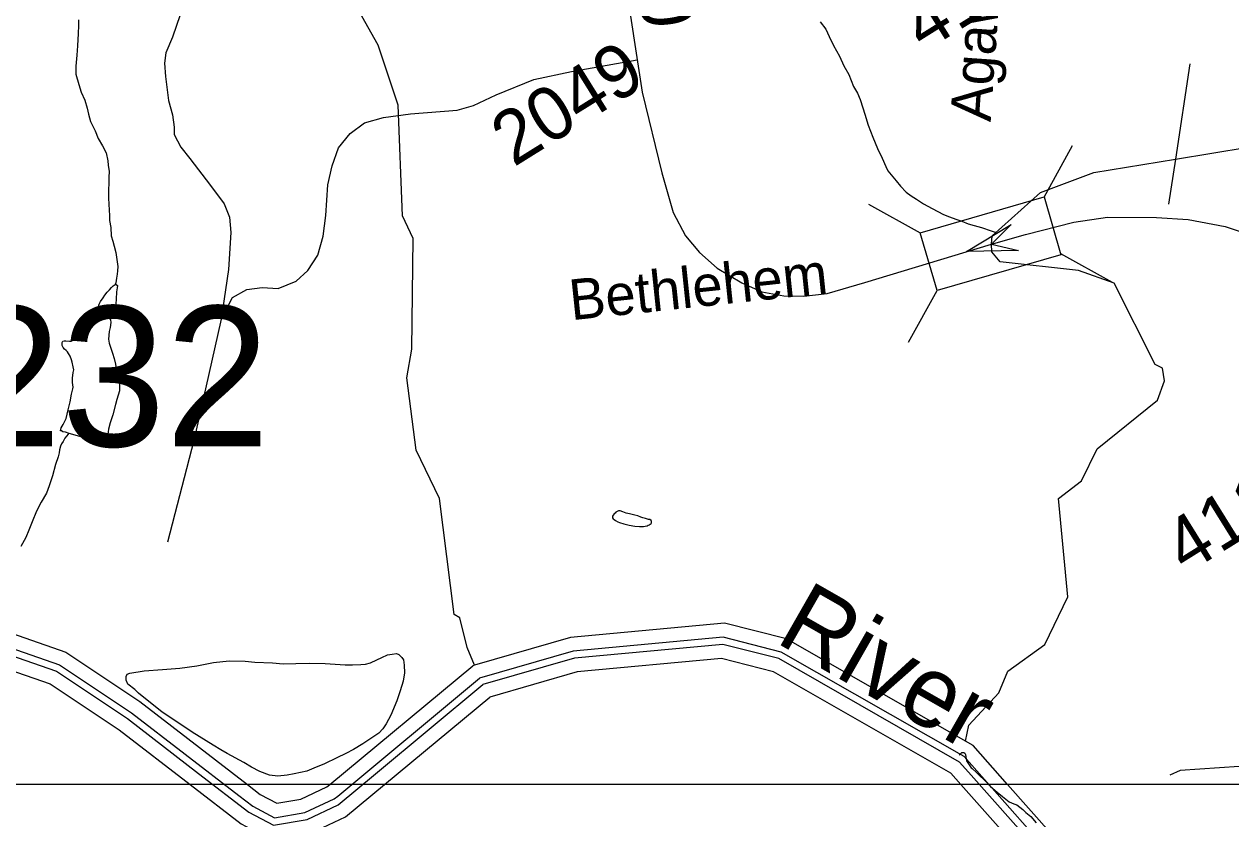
# Model space of a CAD drawing. Extents: x 2001466 to 31450019, y -30647475 to 847247.
# Drawn here: x 2150565 to 2156218, y 718722 to 722442 of the extents above; entities that cross this region are included whole.
import ezdxf

# ---------------------------------------------------------------- set-up
doc = ezdxf.new("R2010")
doc.units = 0
for name, color, linetype in [('Exist Hydrographic Buffer Line', 7, 'Continuous'), ('Exist Hydrographic Creek Single Shore', 7, 'Continuous'), ('Exist Hydrographic Misc Water Feature', 7, 'Continuous'), ('Exist Hydrographic River Shore', 7, 'Continuous'), ('Exist Hydrographic River Shore Label', 7, 'Continuous'), ('Exist Road Non-System Type 51', 7, 'Continuous'), ('Exist Road Secondary Mileage Hundredths English Label', 7, 'Continuous'), ('Exist Road Secondary Structure Standard Bridge Attributed CELL', 7, 'Continuous'), ('Exist Road Secondary Structure Standard Bridge CELL', 7, 'Continuous'), ('Exist Road Secondary Structure Standard Bridge Number Label', 7, 'Continuous'), ('Exist Road Secondary Type 51 Attributed', 7, 'Continuous'), ('Exist Road Secondary Type 51 Label', 7, 'Continuous'), ('Exist Road Secondary Type 51 Number Label', 7, 'Continuous'), ('Map Preparation Inset Cut Line', 7, 'Continuous')]:
    doc.layers.add(name, color=color, linetype=linetype)

msp = doc.modelspace()

# ---------------------------------------------------------------- linework, layer by layer
at = {"layer": 'Exist Hydrographic Buffer Line'}
for p, q in [((2152034.3, 718828.8), (2152699.3, 719379.8)), ((2152212.1, 718933.4), (2152714.9, 719350.2)), ((2155123.4, 718839.4), (2154968.6, 719013.7)), ((2155002.2, 718926.5), (2154947.7, 718987.9))]:
    msp.add_line(p, q, dxfattribs=at)
for points in [[(2148481.3, 719308.3), (2149005.6, 719433.8), (2149630.9, 719486.7), (2150073, 719573), (2150393.3, 719559.8), (2150731.4, 719443.3), (2151068.7, 719218.4), (2151571.1, 718831)], [(2154968.6, 719013.7), (2154112.4, 719502.7), (2153840.5, 719571.7), (2153137.1, 719506.8), (2152699.3, 719379.8)], [(2148486, 719275.6), (2149010.8, 719401.4), (2149635.4, 719454.2), (2150075.5, 719540.1), (2150387.1, 719527.2), (2150716.7, 719413.6), (2151049.5, 719191.8), (2151382.6, 718934.9)], [(2154947.7, 718987.9), (2154100, 719472), (2153837.9, 719538.5), (2153143.2, 719474.5), (2152714.9, 719350.2)], [(2151382.6, 718934.9), (2151618.2, 718753.2), (2151733.5, 718691.9), (2151891.1, 718719.7), (2152036, 718787.5), (2152212.1, 718933.4)], [(2155296.9, 718594.5), (2155002.2, 718926.5)], [(2151571.1, 718831), (2151636, 718780.9), (2151738.9, 718726.2), (2151881.1, 718751.3), (2152018.3, 718815.5), (2152034.3, 718828.8)], [(2155325.2, 718612), (2155123.4, 718839.4)]]:
    msp.add_lwpolyline(points, dxfattribs=at)
at = {"layer": 'Exist Hydrographic Creek Single Shore'}
for points in [[(2155958.2, 721810.2), (2156300, 721866.7), (2156766.1, 722011.4), (2156882.2, 722087.7), (2156907.2, 722169.2), (2156940.2, 722188.2)], [(2154975.6, 719085.3), (2154991.2, 719160.9), (2155132, 719312.2), (2155173.1, 719413), (2155347.1, 719537.4), (2155454.2, 719761.6), (2155410.1, 720221.7), (2155518.2, 720304.8), (2155592.2, 720454.2), (2155874.1, 720681.3), (2155907.1, 720772.5), (2155898.1, 720831.7), (2155864.1, 720848.8), (2155671.1, 721230), (2155504, 721289.2), (2155137.8, 721330.1), (2155098.3, 721375.6), (2155096.8, 721412.2), (2155100.5, 721451.8), (2155327.1, 721653.7), (2155576.2, 721747), (2155958.2, 721810.2)]]:
    msp.add_lwpolyline(points, dxfattribs=at)
at = {"layer": 'Exist Hydrographic Misc Water Feature'}
msp.add_line((2150947.3, 721103.3), (2150942.2, 721079.3), dxfattribs=at)
for points in [[(2152675, 719441.1), (2152640.1, 719523.8), (2152606.2, 719662.3), (2152580.2, 719679.2), (2152511.1, 720221.9), (2152401.2, 720447.2), (2152358.1, 720786), (2152382.1, 720920), (2152387.2, 721438.2), (2152337.2, 721544.2), (2152317.1, 722062.9), (2152224.2, 722343.6), (2152056.3, 722642.3), (2151988.2, 722843.8), (2151986.1, 723132.5), (2152027.1, 723374.4), (2152027.4, 723375.1)], [(2150820, 722461.9), (2150820, 722436), (2150818, 722398.1), (2150814.7, 722340.2), (2150812.8, 722296.3), (2150807.1, 722246), (2150807.7, 722208.3), (2150821.6, 722160.3), (2150831.9, 722124.3), (2150849.7, 722086.7), (2150860, 722048.6), (2150866.4, 722020.5), (2150876.4, 721986.5), (2150898.5, 721942.6), (2150912.9, 721906.8), (2150933.2, 721872.8), (2150949.2, 721839.2), (2150957.8, 721803), (2150959.6, 721781.2), (2150963.8, 721753), (2150961.7, 721725.4), (2150962.3, 721695.3), (2150960.5, 721669.2), (2150960.5, 721631), (2150962.5, 721597), (2150963.1, 721575.1), (2150965, 721543.1), (2150965.2, 721523.3), (2150971.3, 721489.4), (2150973.6, 721451.4), (2150981.6, 721425.5), (2150987.5, 721403.4), (2150995.7, 721373.4), (2150998.2, 721351.5), (2151004.4, 721307.6), (2151002.3, 721287.6), (2151000.5, 721271.7), (2150998.8, 721253.7), (2150994.7, 721231.6), (2150992.5, 721223.4)], [(2154294.8, 722453.5), (2154321.1, 722417.9), (2154337.1, 722383.9), (2154357.4, 722342.3), (2154385.7, 722292.2), (2154406, 722246.5), (2154428.3, 722206.6), (2154450.5, 722150.5), (2154468.5, 722119), (2154481, 722088.7), (2154495, 722050.9), (2154503.2, 722020.9), (2154519.1, 721969), (2154541.7, 721913.2), (2154562.2, 721859.4), (2154584.2, 721815.5), (2154602.6, 721775.8), (2154610.8, 721755.5), (2154634.6, 721728), (2154650.8, 721708.1), (2154671.1, 721683.9), (2154696.9, 721656.1), (2154721.3, 721638.3), (2154745.3, 721622.4), (2154779.2, 721600.7), (2154819.8, 721578.7), (2154845.4, 721565.1), (2154871.6, 721551.4), (2154899.9, 721539.4), (2154929.7, 721529.6), (2154957.8, 721519.7), (2154987.7, 721507.9), (2155015.8, 721500), (2155049.8, 721490.4), (2155096, 721474.5), (2155118.1, 721466.7)], [(2150947.3, 721103.3), (2150943.5, 721107.1), (2150925.4, 721111.1), (2150911.7, 721115.2), (2150917.2, 721131), (2150922.9, 721143.1), (2150935.5, 721161.1), (2150943.2, 721173.3), (2150955.1, 721187.3), (2150965.2, 721199.1), (2150974.8, 721209.4), (2150983, 721217.5), (2150992.5, 721223.4)], [(2150992.5, 721223.4), (2150996.8, 721223.6), (2151002.9, 721219.4), (2151000.9, 721207.5), (2150998.8, 721189.6), (2150998.8, 721179.5), (2150997, 721163.5), (2150997.2, 721151.7), (2150995.3, 721135.4), (2150993.5, 721119.4), (2150995.3, 721107.8), (2150995.5, 721093.5), (2150995.3, 721089.5), (2150989.2, 721091.6), (2150973.4, 721095.3), (2150957.4, 721101.4), (2150947.3, 721103.3)], [(2150776.5, 720526.4), (2150758.9, 720532.3), (2150746.4, 720534.2), (2150740.7, 720538.3), (2150736.3, 720538.1), (2150738.8, 720552.4), (2150748.7, 720568.3), (2150762.2, 720596.2), (2150772.4, 720636.5), (2150781.7, 720674.5), (2150787.6, 720710.4), (2150793.4, 720734.3), (2150795.6, 720742.5), (2150791.5, 720764.6), (2150791.5, 720784.5), (2150795.4, 720810.7), (2150798.9, 720824.4), (2150795, 720838.4), (2150790.9, 720860.4), (2150787, 720870.3), (2150780.6, 720888.3), (2150772.6, 720900.5), (2150768.7, 720908.4), (2150762.6, 720914.2), (2150754.6, 720920.3), (2150748.2, 720928.2), (2150744.3, 720938.1), (2150744.1, 720952.3), (2150746.4, 720958.1), (2150752.3, 720960.4), (2150760.3, 720960.4), (2150778.4, 720958.5), (2150786.4, 720958.5), (2150800.1, 720964.5), (2150807.9, 720972.7), (2150815.9, 720982.4), (2150830.3, 721002.5), (2150832.3, 721008.7), (2150837.8, 721024.5), (2150851.8, 721054.8), (2150861.8, 721068.8), (2150879.5, 721081.1), (2150897.7, 721083.2), (2150915.6, 721082.9), (2150923.8, 721081.3), (2150942.2, 721079.3)], [(2150942.2, 721079.3), (2150957.4, 721071.3), (2150963.5, 721067.5), (2150969.5, 721057.3), (2150971.7, 721045.6), (2150967.9, 721021.5), (2150964, 721003.4), (2150960.1, 720967.5), (2150964.4, 720949.4), (2150978.7, 720901.4), (2150986.7, 720877.5), (2150992.7, 720849.8), (2150997, 720829.7), (2151005, 720803.7), (2151007.6, 720775.8), (2151011.5, 720755.7), (2151011.5, 720725.7), (2150999.8, 720685.6), (2150993.7, 720661.9), (2150980.2, 720613.6), (2150968.3, 720575.6), (2150960.7, 720545.5), (2150956.8, 720521.4), (2150952.9, 720505.3), (2150952.7, 720499.7), (2150952.7, 720479.4), (2150923.2, 720485.5), (2150889.1, 720495.1), (2150860.8, 720501), (2150830.9, 720510.8), (2150805, 720518.8), (2150776.5, 720526.4)], [(2150776.5, 720526.4), (2150771.2, 720522.3), (2150756.6, 720504.2), (2150748.9, 720488.3), (2150740.9, 720478.2), (2150735.1, 720466.1), (2150731, 720450.1), (2150729.2, 720436.1), (2150725.5, 720416.5), (2150711.7, 720380.4), (2150698, 720328.1), (2150682.4, 720280.2), (2150670.3, 720245.9), (2150644.7, 720204), (2150623.2, 720161.8), (2150602.9, 720111.7), (2150587.7, 720073.5), (2150573.9, 720039.4), (2150549.8, 719997.2)], [(2153426.4, 720143.4), (2153401.8, 720149.6), (2153385.8, 720153.2), (2153369.8, 720159.3), (2153357.7, 720163.1), (2153354, 720163.3), (2153349.7, 720163.1), (2153344, 720161.2), (2153337.6, 720157.2), (2153333.9, 720152.9), (2153330.1, 720149.1), (2153324.3, 720143), (2153321.8, 720138.9), (2153322.1, 720134.9), (2153321.8, 720130.8), (2153324.1, 720126.8), (2153329.8, 720123.1), (2153336, 720119), (2153346, 720113), (2153354.5, 720109.3), (2153374.1, 720103.4), (2153400.4, 720097.4), (2153426.2, 720091.5), (2153448.4, 720089.8), (2153456.6, 720089.8), (2153466.4, 720089.9), (2153474.4, 720092), (2153484.5, 720094.1), (2153488.1, 720096), (2153494.5, 720097.9), (2153498.6, 720102.1), (2153502.3, 720104), (2153504.1, 720108.1), (2153504.3, 720113.8), (2153502.1, 720118.2), (2153496.1, 720123.9), (2153490.2, 720124), (2153476, 720127.8), (2153464, 720131.6), (2153454.1, 720133.5), (2153440.2, 720139.7), (2153426.4, 720143.4)], [(2152341.9, 719465.8), (2152346.4, 719441.5), (2152346.8, 719405.8), (2152340.7, 719365.8), (2152327.3, 719321.5), (2152311.1, 719273.7), (2152283.7, 719207.3), (2152261.9, 719167.1), (2152246.1, 719143.2), (2152226.3, 719123.1), (2152194.1, 719101.1), (2152152.4, 719072.6), (2152108.6, 719046.3), (2152072.7, 719028.3), (2152030.6, 719008.2), (2151973.2, 718979.6), (2151923.2, 718959.6), (2151889.4, 718945.3), (2151831.1, 718933), (2151797.5, 718926.7), (2151753.4, 718922.4), (2151715.3, 718926.1), (2151669.3, 718944), (2151631, 718964), (2151595.1, 718985.7), (2151516.6, 719027.2), (2151486.8, 719045.1), (2151450.5, 719066.8), (2151352.5, 719128.3), (2151209.8, 719223.3), (2151141.3, 719277), (2151101.5, 719310.6), (2151083.3, 719326.8), (2151051.1, 719352.3), (2151043.1, 719370.6), (2151042.9, 719380.3), (2151043.1, 719388.4), (2151048.8, 719398.5), (2151060.9, 719404.4), (2151127, 719414.7), (2151212.9, 719421.1), (2151294.9, 719427.8), (2151374.7, 719438.1), (2151452.8, 719454.6), (2151526.4, 719460.9), (2151600.6, 719459.4), (2151646.2, 719455.8), (2151728.6, 719452.3), (2151778.4, 719448.4), (2151838.5, 719449), (2151900.4, 719451), (2151976.3, 719449.7), (2152068.6, 719442.2), (2152104.3, 719442.5), (2152142.4, 719444.4), (2152164.5, 719446.8), (2152188.5, 719452.9), (2152218.1, 719467.1), (2152241.8, 719477.3), (2152268.1, 719489.1), (2152290, 719493.5), (2152309.9, 719495.4), (2152320.4, 719491.7), (2152334.1, 719477.5), (2152341.9, 719465.8)], [(2154945.7, 719020.5), (2154949.8, 719024.7), (2154958, 719032.4), (2154963.9, 719032.7), (2154967.6, 719032.6), (2154971.7, 719028.7), (2154975.8, 719022.8), (2154977.6, 719000.6), (2154980.1, 718994.6), (2154982, 718990.6), (2154986.1, 718984.7), (2155002, 718960.8), (2155006.1, 718956.9), (2155026, 718939), (2155040.4, 718925), (2155064.4, 718903.1), (2155092.5, 718873.3), (2155123, 718847.6), (2155148.7, 718825.9), (2155179.2, 718801.8), (2155201.4, 718792), (2155215.1, 718788.2), (2155243, 718766.2), (2155257.1, 718752.3), (2155281.5, 718732.4), (2155305.5, 718702.8)]]:
    msp.add_lwpolyline(points, dxfattribs=at)
at = {"layer": 'Exist Hydrographic River Shore'}
for p, q in [((2152675, 719441.1), (2152667.9, 719439)), ((2151996.8, 718882.9), (2152667.9, 719439)), ((2152253.9, 718882.9), (2152746.3, 719291)), ((2155010.6, 719065.4), (2154975.6, 719085.3)), ((2155172.5, 718882.9), (2155010.6, 719065.4)), ((2154953.1, 718882.9), (2154905.8, 718936.3))]:
    msp.add_line(p, q, dxfattribs=at)
for points in [[(2148472.1, 719373.5), (2148995.1, 719498.8), (2149621.8, 719551.8), (2150068, 719638.9), (2150405.6, 719625), (2150760.8, 719502.6), (2151106.9, 719271.8), (2151611.2, 718882.9)], [(2154975.6, 719085.3), (2154137.2, 719564.1), (2153845.7, 719638.1), (2153124.8, 719571.6), (2152675, 719441.1)], [(2148495.2, 719210.4), (2149021.3, 719336.4), (2149644.5, 719389.1), (2150080.5, 719474.2), (2150374.8, 719462), (2150687.3, 719354.4), (2151011.3, 719138.4), (2151342.6, 718882.9)], [(2154905.8, 718936.3), (2154075.2, 719410.6), (2153832.7, 719472.1), (2153155.5, 719409.7), (2152746.3, 719291)], [(2151342.6, 718882.9), (2151582.5, 718697.9), (2151722.6, 718623.4), (2151911, 718656.6), (2152071.4, 718731.7), (2152253.9, 718882.9)], [(2151611.2, 718882.9), (2151671.7, 718836.2), (2151749.8, 718794.7), (2151861.1, 718814.4), (2151982.9, 718871.4), (2151996.8, 718882.9)], [(2155240.3, 718559.4), (2154953.1, 718882.9)], [(2155381.8, 718647.1), (2155172.5, 718882.9)]]:
    msp.add_lwpolyline(points, dxfattribs=at)
at = {"layer": 'Exist Road Non-System Type 51'}
for p, q in [((2156025.4, 722256.7), (2155958.2, 721810.2)), ((2155958.2, 721810.2), (2155926.5, 721599.5))]:
    msp.add_line(p, q, dxfattribs=at)
for points in [[(2151295.8, 722485.3), (2151260.5, 722381.3), (2151229, 722307.1), (2151223.2, 722259), (2151227.5, 722197.2), (2151242.2, 722085.3), (2151260.5, 722017.3), (2151268.9, 721959.4), (2151269, 721925.6), (2151299.3, 721865.7), (2151341.7, 721813.9), (2151438.3, 721686.5), (2151502.7, 721600.8), (2151527, 721539.2), (2151533.6, 721467), (2151522.6, 721293.1), (2151487.9, 721061), (2151429.3, 720796.9), (2151361, 720492.5), (2151237.7, 720017.9)], [(2151487.9, 721061), (2151541.1, 721162.4), (2151608.5, 721200.4), (2151680.2, 721208.8), (2151756, 721204.6), (2151840.3, 721238.3), (2151895.1, 721288.9), (2151941.5, 721360.6), (2151966.7, 721449.2), (2151979.4, 721546.2), (2151987.8, 721689.6), (2152008.9, 721778.1), (2152038.4, 721862.5), (2152093.2, 721929.9), (2152160.6, 721980.5), (2152249.1, 722005.8), (2152375.5, 722022.7), (2152594.7, 722039.6), (2152670.5, 722060.7), (2152775.9, 722111.3), (2152952.9, 722183), (2153129.9, 722220.9), (2153437.9, 722274.7)]]:
    msp.add_lwpolyline(points, dxfattribs=at)
at = {"layer": 'Exist Road Secondary Structure Standard Bridge Attributed CELL'}
msp.add_lwpolyline([(2155223.4, 721382.9), (2154979.6, 721378.6), (2155188.6, 721504.3), (2155096.8, 721412.2)], close=True, dxfattribs=at)
at = {"layer": 'Exist Road Secondary Structure Standard Bridge CELL'}
for p, q in [((2155344, 721632.8), (2155477, 721874.6)), ((2154521.3, 721598.8), (2154763.1, 721465.7)), ((2155420.8, 721367.8), (2155662.6, 721234.7)), ((2154708.7, 720952.8), (2154841.7, 721194.6))]:
    msp.add_line(p, q, dxfattribs=at)
msp.add_lwpolyline([(2154763.1, 721465.7), (2155343.6, 721634.1), (2155422.2, 721362.9), (2154841.7, 721194.6)], close=True, dxfattribs=at)
at = {"layer": 'Exist Road Secondary Type 51 Attributed'}
for points in [[(2153057.5, 725451.9), (2153014.3, 725300.1), (2152993.4, 725180.7), (2152995.5, 725061.3), (2153010.1, 724965), (2153101.2, 724424.7), (2153164, 724060.3), (2153315.7, 723090.6), (2153378.5, 722663.4), (2153461.1, 722123.1), (2153553.2, 721746.1), (2153605.5, 721559.7), (2153664.1, 721450.8), (2153729, 721373.3), (2153811.7, 721300), (2153926.8, 721230.9), (2154020.9, 721189), (2154123.5, 721170.2), (2154217.7, 721168.1), (2154326.5, 721180.7), (2154504.4, 721233), (2155096.8, 721412.2)], [(2155096.8, 721412.2), (2155256.7, 721457.1), (2155482.7, 721515.7), (2155639.7, 721538.8), (2155869.9, 721536.7), (2156018.5, 721528.3), (2156192.2, 721494.8), (2156334.5, 721446.6), (2156517.6, 721371.2), (2156620.2, 721310.5), (2156724.8, 721233), (2156800.1, 721147.1), (2156929.9, 720937.7), (2157067, 720701.1)], [(2158466, 719532.5), (2158371.8, 719364.9), (2158302.8, 719241.4), (2158233.7, 719170.2), (2158162.5, 719124.1), (2158091.4, 719094.8), (2157982.6, 719084.3), (2157085.8, 719023.6), (2155980.8, 718948.2), (2155932.7, 718927.2)]]:
    msp.add_lwpolyline(points, dxfattribs=at)
at = {"layer": 'Map Preparation Inset Cut Line'}
for p, q in [((2151342.6, 718882.9), (2147837.3, 718882.9)), ((2151380.3, 718882.9), (2151342.6, 718882.9)), ((2151397.6, 718882.9), (2151380.3, 718882.9)), ((2151476.9, 718882.9), (2151397.6, 718882.9)), ((2151556.6, 718882.9), (2151476.9, 718882.9)), ((2151578.1, 718882.9), (2151556.6, 718882.9)), ((2151611.2, 718882.9), (2151578.1, 718882.9)), ((2151996.8, 718882.9), (2151611.2, 718882.9)), ((2152029.1, 718882.9), (2151996.8, 718882.9)), ((2152049.1, 718882.9), (2152029.1, 718882.9)), ((2152125.4, 718882.9), (2152049.1, 718882.9)), ((2152201.2, 718882.9), (2152125.4, 718882.9)), ((2152225.3, 718882.9), (2152201.2, 718882.9)), ((2152253.9, 718882.9), (2152225.3, 718882.9)), ((2154953.1, 718882.9), (2152253.9, 718882.9)), ((2154977.7, 718882.9), (2154953.1, 718882.9)), ((2155035, 718882.9), (2154977.7, 718882.9)), ((2155062.8, 718882.9), (2155035, 718882.9)), ((2155114.4, 718882.9), (2155062.8, 718882.9)), ((2155155.5, 718882.9), (2155114.4, 718882.9)), ((2155172.5, 718882.9), (2155155.5, 718882.9)), ((2157924.3, 718882.9), (2155172.5, 718882.9))]:
    msp.add_line(p, q, dxfattribs=at)

# ---------------------------------------------------------------- texts
at = {"layer": 'Exist Hydrographic River Shore Label'}
msp.add_text('River', height=334.64, rotation=330.2737, dxfattribs=at).set_placement((2154077.4, 719552.5))
at = {"layer": 'Exist Road Secondary Mileage Hundredths English Label'}
msp.add_text('1.60', height=250, rotation=277.5129, dxfattribs=at).set_placement((2153381.8, 723057))
at = {"layer": 'Exist Road Secondary Structure Standard Bridge Number Label'}
msp.add_text('232', height=656.17, dxfattribs=at).set_placement((2150251.4, 720465.6))
at = {"layer": 'Exist Road Secondary Type 51 Label'}
for s, rotation, p in [('Agawam Ct.', 86.0471, (2155093.1, 721982.5)), ('Bethlehem', 6.014, (2153128.9, 721055.8))]:
    msp.add_text(s, height=190, rotation=rotation, dxfattribs=at).set_placement(p)
at = {"layer": 'Exist Road Secondary Type 51 Number Label'}
for s, p in [('4120', (2154780.6, 722309.7)), ('2049', (2152858.7, 721771)), ('4110', (2156008, 719864.6))]:
    msp.add_text(s, height=250, rotation=31.918, dxfattribs=at).set_placement(p)

doc.saveas('drawing.dxf')
